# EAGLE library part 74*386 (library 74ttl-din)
Quadruple 2-input EXCLUSIVE-OR gate
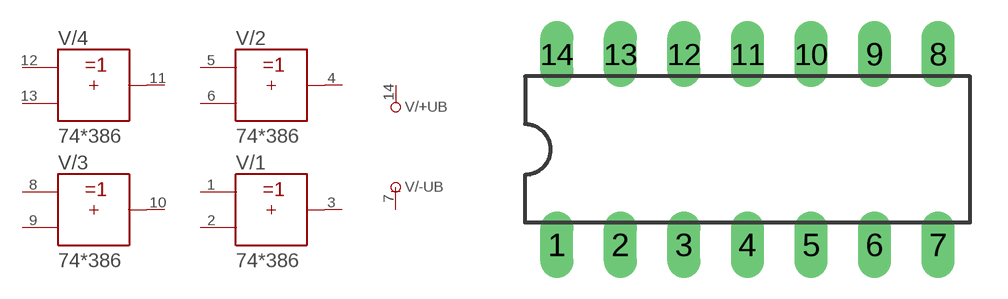
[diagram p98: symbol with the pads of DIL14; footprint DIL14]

Designator prefix V; gates /+UB=+UB /-UB=-UB /1=386 /2=386 /3=386 /4=386

## 74386N  [DIL14]
1  /1:A  in
2  /1:B  in
3  /1:Y  out
4  /2:Y  out
5  /2:A  in
6  /2:B  in
7  /-UB:-UB  pwr
8  /3:A  in
9  /3:B  in
10  /3:Y  out
11  /4:Y  out
12  /4:A  in
13  /4:B  in
14  /+UB:+UB  pwr

## Footprint DIL14 (pad centres in mm)
Dual In Line Package
drill 0.813 long: 1 -7.62,-3.81; 2 -5.08,-3.81; 3 -2.54,-3.81; 4 0,-3.81; 5 2.54,-3.81; 6 5.08,-3.81; 7 7.62,-3.81; 8 7.62,3.81; 9 5.08,3.81; 10 2.54,3.81; 11 0,3.81; 12 -2.54,3.81; 13 -5.08,3.81; 14 -7.62,3.81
